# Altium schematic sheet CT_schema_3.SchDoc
size 334 x 183 mm
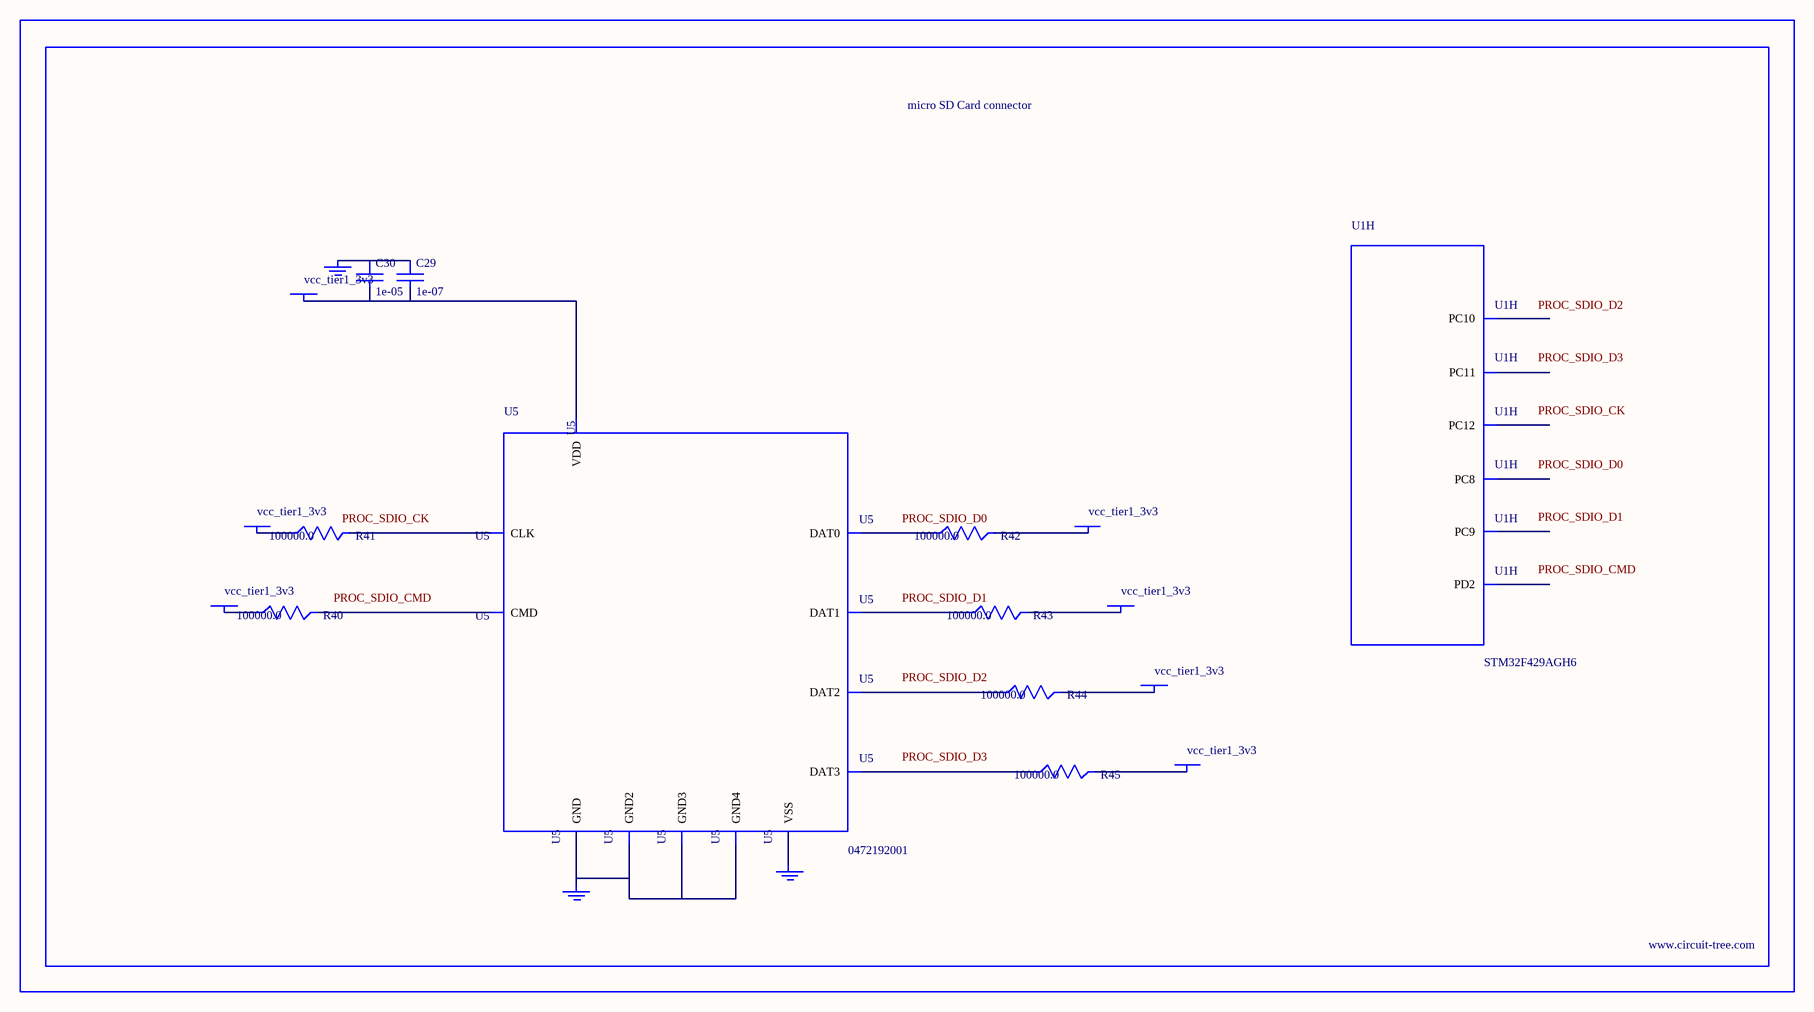
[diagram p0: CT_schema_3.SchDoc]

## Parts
BORDER2  (no value)
C29  1e-07  [C0402]
C30  1e-05  [C0805]
GND_INSTANCE_2_0  (no value)
GND_INSTANCE_2_1  (no value)
GND_INSTANCE_2_2  (no value)
POWER_INSTANCE_2_0  vcc_tier1_3v3
POWER_INSTANCE_2_1  vcc_tier1_3v3
POWER_INSTANCE_2_2  vcc_tier1_3v3
POWER_INSTANCE_2_3  vcc_tier1_3v3
POWER_INSTANCE_2_4  vcc_tier1_3v3
POWER_INSTANCE_2_5  vcc_tier1_3v3
POWER_INSTANCE_2_6  vcc_tier1_3v3
R40  100000.0  [R0603]
R41  100000.0  [R0603]
R42  100000.0  [R0603]
R43  100000.0  [R0603]
R44  100000.0  [R0603]
R45  100000.0  [R0603]
U1  STM32F429AGH6  [UFBGA169]  (part H of 11)
U5  0472192001  [MOLEX_47219-2001]

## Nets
NetC29_1: C29.1 C30.1 GND_INSTANCE_2_0.0(GND)
NetC29_2: C29.2 C30.2 POWER_INSTANCE_2_3.0(PWR) U5.4(VDD)
NetGND_INSTANCE_2_1_0: GND_INSTANCE_2_1.0(GND) U5.6(VSS)
NetGND_INSTANCE_2_2_0: GND_INSTANCE_2_2.0(GND) U5.G1(GND) U5.G2(GND2) U5.G3(GND3) U5.G4(GND4)
NetPOWER_INSTANCE_2_0_0: POWER_INSTANCE_2_0.0(PWR) R44.2
NetPOWER_INSTANCE_2_1_0: POWER_INSTANCE_2_1.0(PWR) R45.2
NetPOWER_INSTANCE_2_2_0: POWER_INSTANCE_2_2.0(PWR) R40.1
NetPOWER_INSTANCE_2_4_0: POWER_INSTANCE_2_4.0(PWR) R41.1
NetPOWER_INSTANCE_2_5_0: POWER_INSTANCE_2_5.0(PWR) R42.2
NetPOWER_INSTANCE_2_6_0: POWER_INSTANCE_2_6.0(PWR) R43.2
NetR40_2: R40.2 U5.3(CMD)
NetR41_2: R41.2 U5.5(CLK)
NetR42_1: R42.1 U5.7(DAT0)
NetR43_1: R43.1 U5.8(DAT1)
NetR44_1: R44.1 U5.1(DAT2)
NetR45_1: R45.1 U5.2(DAT3)

Not connected (* = marked no-connect by the designer): U1 A10(PC12) B9(PD2) B10(PC11) C10(PC10) F11(PC8) F12(PC9)

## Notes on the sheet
- Labels drawn without touching a wire or pin: PROC_SDIO_CK, PROC_SDIO_CMD, PROC_SDIO_D0, PROC_SDIO_D1, PROC_SDIO_D2, PROC_SDIO_D3

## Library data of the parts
BORDER2 = BORDER_PAGE2
C29 = C0402C104K3RACTU
C30 = C0805C106K8RACTU
GND_INSTANCE_2_0-GND_INSTANCE_2_2 = GND
POWER_INSTANCE_2_0-POWER_INSTANCE_2_6 = PWR
R40-R45 = RC0603JR-07100KL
